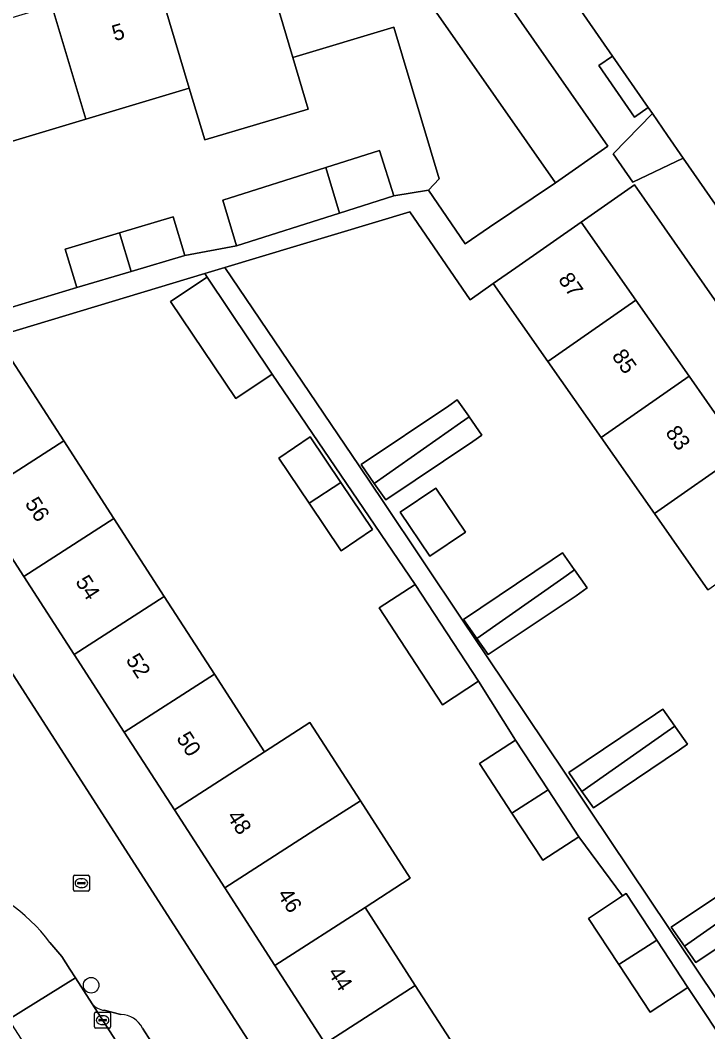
# Model space of a CAD drawing. Extents: x 159352 to 160617, y 385888 to 387323.
# Drawn here: x 159749 to 159792.3, y 386318 to 386381.5 of the extents above; entities that cross this region are included whole.
import ezdxf

# ---------------------------------------------------------------- set-up
doc = ezdxf.new("R2010")
doc.units = 0
for name, color, linetype in [('IMGEO_Boom', 7, 'Continuous'), ('IMGEO_Erf', 7, 'Continuous'), ('IMGEO_Kolk', 7, 'Continuous'), ('IMGEO_Pand', 7, 'Continuous'), ('IMGEO_Pand_nummerreeks', 7, 'Continuous'), ('IMGEO_Parkeervlak_open', 7, 'Continuous'), ('IMGEO_Rijbaan_lokaal_gesloten', 7, 'Continuous'), ('IMGEO_Rijbaan_lokaal_open', 7, 'Continuous'), ('IMGEO_Rioolput', 7, 'Continuous'), ('IMGEO_Voetpad_open', 7, 'Continuous')]:
    doc.layers.add(name, color=color, linetype=linetype)

msp = doc.modelspace()

# ---------------------------------------------------------------- linework, layer by layer
at = {"layer": 'IMGEO_Boom'}
msp.add_circle((159753.496, 386320.884), 0.489, dxfattribs=at)
at = {"layer": 'IMGEO_Erf'}
for points in [[(159764.051, 386386.334), (159770.708, 386388.324), (159771.938, 386384.207), (159773.381, 386384.639), (159782.695, 386371.311), (159785.983, 386373.605), (159773.422, 386391.613)], [(159746.351, 386362.856), (159752.592, 386364.728), (159751.872, 386367.146), (159755.287, 386368.163), (159758.658, 386369.167), (159759.378, 386366.749), (159762.637, 386367.359), (159761.779, 386370.231), (159768.247, 386372.277), (159771.626, 386373.346), (159772.53, 386370.489), (159774.705, 386370.856), (159775.37, 386371.561), (159772.522, 386381.09), (159766.182, 386379.195), (159767.151, 386375.948), (159760.638, 386374.003), (159759.669, 386377.249), (159753.156, 386375.302), (159746.642, 386373.355)], [(159815.949, 386330.644), (159787.666, 386371.193), (159784.299, 386368.844), (159787.734, 386363.946), (159791.085, 386359.167), (159794.436, 386354.389)], [(159792.268, 386345.742), (159788.917, 386350.52), (159785.566, 386355.299), (159782.215, 386360.077), (159778.781, 386364.974), (159777.332, 386363.957), (159773.534, 386369.495), (159761.909, 386365.991), (159770.355, 386353.528), (159771.86, 386351.282), (159776.851, 386343.834), (159778.356, 386341.588), (159783.346, 386334.141), (159784.851, 386331.895), (159789.842, 386324.447), (159791.347, 386322.201), (159794.738, 386317.142)], [(159793.797, 386316.542), (159791.022, 386320.752), (159788.643, 386319.195), (159786.671, 386322.188), (159784.762, 386325.083), (159786.901, 386326.492), (159784.156, 386330.214), (159781.898, 386328.735), (159779.953, 386331.706), (159777.919, 386334.812), (159780.178, 386336.291), (159777.843, 386339.993), (159775.585, 386338.514), (159771.606, 386344.591), (159773.865, 386346.07), (159764.875, 386359.296), (159762.584, 386357.757), (159758.495, 386363.843), (159760.786, 386365.382), (159760.635, 386365.607), (159738.213, 386358.849), (159740.771, 386352.514), (159758.089, 386325.63), (159772.624, 386303.066)], [(159768.209, 386317.23), (159765.052, 386322.12), (159761.895, 386327.009), (159758.737, 386331.898), (159755.58, 386336.788), (159752.423, 386341.677), (159749.266, 386346.566), (159746.109, 386351.455), (159742.87, 386356.47), (159747.075, 386359.177), (159748.538, 386360.118), (159751.777, 386355.101), (159754.933, 386350.211), (159758.089, 386345.322), (159761.245, 386340.432), (159764.402, 386335.542), (159767.253, 386337.404), (159770.438, 386332.472), (159773.562, 386327.616), (159770.715, 386325.763), (159773.871, 386320.873), (159777.027, 386315.983)], [(159796.983, 386325.978), (159791.522, 386322.318), (159790.807, 386323.338), (159789.97, 386324.533), (159795.478, 386328.224)]]:
    msp.add_lwpolyline(points, dxfattribs=at)
for points in [[(159772.019, 386351.388), (159771.295, 386352.422), (159770.466, 386353.604), (159775.992, 386357.305), (159776.517, 386357.673), (159777.238, 386356.644), (159777.264, 386356.607), (159778.068, 386355.459), (159777.497, 386355.059)], [(159769.209, 386348.188), (159767.197, 386351.181), (159765.296, 386354.01), (159767.275, 386355.34), (159769.202, 386352.471), (159771.187, 386349.517)], [(159774.782, 386347.846), (159772.931, 386350.608), (159775.177, 386352.113), (159777.027, 386349.351)], [(159782.487, 386347.611), (159783.132, 386348.063), (159783.867, 386347.014), (159783.89, 386346.982), (159784.683, 386345.85), (159783.992, 386345.365), (159778.462, 386341.659), (159777.748, 386342.677), (159776.91, 386343.872)], [(159788.982, 386337.918), (159789.444, 386338.242), (159790.202, 386337.161), (159790.235, 386337.112), (159790.995, 386336.028), (159790.487, 386335.672), (159785.072, 386332.043), (159784.357, 386333.063), (159783.521, 386334.256)]]:
    msp.add_lwpolyline(points, close=True, dxfattribs=at)
at = {"layer": 'IMGEO_Kolk'}
for p, q in [((159753.791, 386319.189), (159754.643, 386319.189)), ((159753.716, 386318.263), (159753.716, 386319.115)), ((159753.975, 386318.683), (159753.975, 386318.695)), ((159754.413, 386318.646), (159754.015, 386318.646)), ((159754.018, 386318.732), (159754.416, 386318.732)), ((159754.204, 386318.969), (159754.229, 386318.969)), ((159754.459, 386318.695), (159754.459, 386318.683)), ((159754.717, 386319.115), (159754.717, 386318.263)), ((159754.643, 386318.189), (159753.791, 386318.189)), ((159754.227, 386318.409), (159754.202, 386318.409))]:
    msp.add_line(p, q, dxfattribs=at)
for points in [[(159753.791, 386319.189), (159754.643, 386319.189)], [(159753.716, 386318.263), (159753.716, 386319.115)], [(159754.717, 386319.115), (159754.717, 386318.263)], [(159754.643, 386318.189), (159753.791, 386318.189)]]:
    msp.add_lwpolyline(points, dxfattribs=at)
for centre, radius, start, end in [((159753.793, 386319.113), 0.0765, 91.55205, 178.44795), ((159753.793, 386319.113), 0.0765, 91.55205, 178.44795), ((159754.641, 386319.113), 0.0765, 1.55205, 88.44795), ((159754.641, 386319.113), 0.0765, 1.55205, 88.44795), ((159754.015, 386318.692), 0.0403, 85.87752, 175.75265), ((159754.012, 386318.682), 0.0366, 178.93798, 274.71019), ((159754.416, 386318.689), 0.043, 264.86636, 352.45326), ((159754.42, 386318.694), 0.0386, 1.73085, 96.63898), ((159753.793, 386318.265), 0.0765, 181.55205, 268.44795), ((159753.793, 386318.265), 0.0765, 181.55205, 268.44795), ((159754.641, 386318.265), 0.0765, 271.55205, 358.44795), ((159754.641, 386318.265), 0.0765, 271.55205, 358.44795)]:
    msp.add_arc(centre, radius, start, end, dxfattribs=at)
for centre, major_axis, ratio, start_param, end_param in [((159754.203, 386318.689), (-0.387, 0.002), 0.722429, 4.712389, 7.853982), ((159754.228, 386318.689), (-0.39, 0.002), 0.717154, 1.570796, 4.712389)]:
    msp.add_ellipse(centre, major_axis=major_axis, ratio=ratio, start_param=start_param, end_param=end_param, dxfattribs=at)
at = {"layer": 'IMGEO_Pand'}
for points in [[(159766.182, 386379.195), (159772.522, 386381.09), (159775.37, 386371.561), (159774.705, 386370.856), (159777.015, 386367.477), (159778.551, 386368.514), (159782.695, 386371.311), (159773.381, 386384.639), (159771.938, 386384.207), (159770.708, 386388.324), (159764.051, 386386.334)], [(159764.051, 386386.334), (159757.538, 386384.388), (159759.669, 386377.249), (159760.638, 386374.003), (159767.151, 386375.948), (159766.182, 386379.195)], [(159757.538, 386384.388), (159751.025, 386382.441), (159753.156, 386375.302), (159759.669, 386377.249)], [(159746.642, 386373.355), (159753.156, 386375.302), (159751.025, 386382.441), (159744.511, 386380.494)], [(159772.53, 386370.489), (159771.626, 386373.346), (159768.247, 386372.277), (159769.104, 386369.405)], [(159761.779, 386370.231), (159762.637, 386367.359), (159769.104, 386369.405), (159768.247, 386372.277)], [(159759.378, 386366.749), (159758.658, 386369.167), (159755.287, 386368.163), (159756.009, 386365.746)], [(159787.734, 386363.946), (159784.299, 386368.844), (159780.206, 386365.974), (159778.781, 386364.974), (159782.215, 386360.077)], [(159751.872, 386367.146), (159752.592, 386364.728), (159756.009, 386365.746), (159755.287, 386368.163)], [(159758.495, 386363.843), (159762.584, 386357.757), (159764.875, 386359.296), (159760.786, 386365.382)], [(159791.085, 386359.167), (159787.734, 386363.946), (159782.215, 386360.077), (159785.566, 386355.299)], [(159751.777, 386355.101), (159748.538, 386360.118), (159747.075, 386359.177), (159742.87, 386356.47), (159746.109, 386351.455)], [(159785.566, 386355.299), (159788.917, 386350.52), (159794.436, 386354.389), (159791.085, 386359.167)], [(159776.717, 386356.223), (159777.264, 386356.607), (159777.238, 386356.644), (159776.517, 386357.673), (159775.992, 386357.305), (159770.466, 386353.604), (159771.295, 386352.422)], [(159777.497, 386355.059), (159778.068, 386355.459), (159777.264, 386356.607), (159776.717, 386356.223), (159771.295, 386352.422), (159772.019, 386351.388)], [(159746.109, 386351.455), (159749.266, 386346.566), (159754.933, 386350.211), (159751.777, 386355.101)], [(159767.275, 386355.34), (159765.296, 386354.01), (159767.197, 386351.181), (159769.202, 386352.471)], [(159788.917, 386350.52), (159792.268, 386345.742), (159797.786, 386349.611), (159794.436, 386354.389)], [(159769.202, 386352.471), (159767.197, 386351.181), (159769.209, 386348.188), (159771.187, 386349.517)], [(159772.931, 386350.608), (159774.782, 386347.846), (159777.027, 386349.351), (159775.177, 386352.113)], [(159758.089, 386345.322), (159754.933, 386350.211), (159749.266, 386346.566), (159752.423, 386341.677)], [(159783.222, 386346.514), (159783.89, 386346.982), (159783.867, 386347.014), (159783.132, 386348.063), (159782.487, 386347.611), (159776.91, 386343.872), (159777.748, 386342.677)], [(159783.992, 386345.365), (159784.683, 386345.85), (159783.89, 386346.982), (159783.222, 386346.514), (159777.748, 386342.677), (159778.462, 386341.659)], [(159771.606, 386344.591), (159775.585, 386338.514), (159777.843, 386339.993), (159773.865, 386346.07)], [(159761.245, 386340.432), (159758.089, 386345.322), (159752.423, 386341.677), (159755.58, 386336.788)], [(159755.58, 386336.788), (159758.737, 386331.898), (159764.402, 386335.542), (159761.245, 386340.432)], [(159789.717, 386336.821), (159790.202, 386337.161), (159789.444, 386338.242), (159788.982, 386337.918), (159783.521, 386334.256), (159784.357, 386333.063)], [(159770.438, 386332.472), (159767.253, 386337.404), (159764.402, 386335.542), (159758.737, 386331.898), (159761.895, 386327.009), (159767.558, 386330.652)], [(159790.487, 386335.672), (159790.995, 386336.028), (159790.235, 386337.112), (159790.202, 386337.161), (159789.717, 386336.821), (159784.357, 386333.063), (159785.072, 386332.043)], [(159780.178, 386336.291), (159777.919, 386334.812), (159779.953, 386331.706), (159782.224, 386333.166)], [(159781.898, 386328.735), (159784.156, 386330.214), (159782.224, 386333.166), (159779.953, 386331.706)], [(159770.438, 386332.472), (159767.558, 386330.652), (159761.895, 386327.009), (159765.052, 386322.12), (159770.715, 386325.763), (159773.562, 386327.616)], [(159796.213, 386327.127), (159796.833, 386327.562), (159796.076, 386328.643), (159795.478, 386328.224), (159789.97, 386324.533), (159790.807, 386323.338)], [(159796.983, 386325.978), (159796.213, 386327.127), (159790.807, 386323.338), (159791.522, 386322.318)], [(159786.901, 386326.492), (159784.762, 386325.083), (159786.671, 386322.188), (159789.063, 386323.725), (159787.137, 386326.648)], [(159773.871, 386320.873), (159770.715, 386325.763), (159765.052, 386322.12), (159768.209, 386317.23)], [(159789.063, 386323.725), (159786.671, 386322.188), (159788.643, 386319.195), (159791.022, 386320.752)], [(159768.209, 386317.23), (159771.366, 386312.341), (159777.027, 386315.983), (159773.871, 386320.873)]]:
    msp.add_lwpolyline(points, close=True, dxfattribs=at)
at = {"layer": 'IMGEO_Parkeervlak_open'}
for points in [[(159753.56, 386319.71), (159791.707, 386260.356)], [(159755.374, 386319.05), (159754.322, 386319.308)], [(159791.331, 386264.428), (159771.07, 386295.893), (159769.144, 386298.883), (159768.113, 386300.485), (159766.159, 386303.52), (159756.717, 386318.183)]]:
    msp.add_lwpolyline(points, dxfattribs=at)
for centre, radius, start, end in [((159754.46, 386320.492), 1.192, 221.00835, 263.36307), ((159755.329, 386317.506), 1.545, 25.99201, 88.31787)]:
    msp.add_arc(centre, radius, start, end, dxfattribs=at)
at = {"layer": 'IMGEO_Rijbaan_lokaal_gesloten'}
msp.add_lwpolyline([(159772.135, 386399.664), (159786.274, 386379.271), (159788.514, 386376.04), (159788.78, 386375.657), (159789.737, 386374.277), (159790.721, 386372.862), (159806.321, 386350.42)], dxfattribs=at)
at = {"layer": 'IMGEO_Rijbaan_lokaal_open'}
msp.add_lwpolyline([(159748.295, 386318.74), (159752.513, 386321.34), (159752.155, 386321.898), (159751.651, 386322.683), (159750.909, 386323.567)], dxfattribs=at)
msp.add_lwpolyline([(159753.56, 386319.71), (159752.513, 386321.34), (159748.295, 386318.74), (159758.148, 386303.438), (159760.892, 386299.177), (159787.704, 386257.403), (159787.911, 386257.081), (159792.063, 386259.851), (159791.888, 386260.1), (159791.707, 386260.356)], close=True, dxfattribs=at)
msp.add_arc((159741.546, 386316.454), 11.759, 37.22296, 72.80476, dxfattribs=at)
at = {"layer": 'IMGEO_Rioolput'}
for p, q in [((159752.383, 386326.873), (159752.383, 386327.725)), ((159752.458, 386327.799), (159753.31, 386327.799)), ((159752.871, 386327.579), (159752.896, 386327.579)), ((159753.384, 386327.725), (159753.384, 386326.873)), ((159752.642, 386327.293), (159752.642, 386327.305)), ((159753.08, 386327.256), (159752.682, 386327.256)), ((159752.685, 386327.342), (159753.083, 386327.342)), ((159752.894, 386327.019), (159752.869, 386327.019)), ((159753.126, 386327.305), (159753.126, 386327.293)), ((159753.31, 386326.799), (159752.458, 386326.799))]:
    msp.add_line(p, q, dxfattribs=at)
for points in [[(159752.383, 386326.873), (159752.383, 386327.725)], [(159752.458, 386327.799), (159753.31, 386327.799)], [(159753.384, 386327.725), (159753.384, 386326.873)], [(159753.31, 386326.799), (159752.458, 386326.799)]]:
    msp.add_lwpolyline(points, dxfattribs=at)
for centre, radius, start, end in [((159752.46, 386327.723), 0.0765, 91.55205, 178.44795), ((159752.46, 386327.723), 0.0765, 91.55205, 178.44795), ((159753.308, 386327.723), 0.0765, 1.55205, 88.44795), ((159753.308, 386327.723), 0.0765, 1.55205, 88.44795), ((159752.46, 386326.875), 0.0765, 181.55205, 268.44795), ((159752.46, 386326.875), 0.0765, 181.55205, 268.44795), ((159752.682, 386327.302), 0.0403, 85.87752, 175.75265), ((159752.679, 386327.292), 0.0366, 178.93798, 274.71019), ((159753.083, 386327.299), 0.043, 264.86636, 352.45326), ((159753.087, 386327.304), 0.0386, 1.73085, 96.63898), ((159753.308, 386326.875), 0.0765, 271.55205, 358.44795), ((159753.308, 386326.875), 0.0765, 271.55205, 358.44795)]:
    msp.add_arc(centre, radius, start, end, dxfattribs=at)
for centre, major_axis, ratio, start_param, end_param in [((159752.87, 386327.299), (-0.387, 0.002), 0.722429, 4.712389, 7.853982), ((159752.895, 386327.299), (-0.39, 0.002), 0.717154, 1.570796, 4.712389)]:
    msp.add_ellipse(centre, major_axis=major_axis, ratio=ratio, start_param=start_param, end_param=end_param, dxfattribs=at)
at = {"layer": 'IMGEO_Voetpad_open'}
for points in [[(159806.321, 386350.42), (159790.721, 386372.862), (159787.552, 386371.356), (159786.32, 386373.122), (159788.78, 386375.657), (159788.514, 386376.04), (159787.659, 386375.447), (159785.419, 386378.678), (159786.274, 386379.271), (159772.135, 386399.664), (159771.719, 386400.218), (159771.256, 386400.732), (159770.748, 386401.203), (159770.2, 386401.627), (159769.617, 386402), (159769.003, 386402.319), (159768.362, 386402.582), (159767.701, 386402.788), (159764.562, 386401.86), (159764.565, 386401.845)], [(159773.422, 386391.613), (159785.983, 386373.605), (159782.695, 386371.311), (159778.551, 386368.514), (159777.015, 386367.477), (159774.705, 386370.856), (159772.53, 386370.489), (159769.104, 386369.405), (159762.637, 386367.359), (159759.378, 386366.749), (159756.009, 386365.746), (159752.592, 386364.728), (159746.351, 386362.856)], [(159738.213, 386358.849), (159760.635, 386365.607), (159761.909, 386365.991), (159773.534, 386369.495), (159777.332, 386363.957), (159778.781, 386364.974), (159780.206, 386365.974), (159784.299, 386368.844), (159787.666, 386371.193)], [(159787.666, 386371.193), (159815.949, 386330.644), (159816.573, 386329.75), (159844.806, 386289.272), (159847.524, 386285.715)], [(159794.738, 386317.142), (159791.347, 386322.201), (159789.842, 386324.447), (159784.851, 386331.895), (159783.346, 386334.141), (159778.356, 386341.588), (159776.851, 386343.834), (159771.86, 386351.282), (159770.355, 386353.528), (159761.909, 386365.991), (159760.635, 386365.607), (159760.786, 386365.382), (159764.875, 386359.296), (159773.865, 386346.07), (159777.843, 386339.993), (159780.178, 386336.291), (159782.224, 386333.166), (159784.156, 386330.214), (159786.901, 386326.492), (159787.137, 386326.648), (159789.063, 386323.725), (159791.022, 386320.752), (159793.797, 386316.542)], [(159791.707, 386260.356), (159791.888, 386260.1), (159797.832, 386263.932), (159773.364, 386301.917), (159772.624, 386303.066), (159758.089, 386325.63), (159740.771, 386352.514)], [(159750.909, 386323.567), (159751.651, 386322.683), (159752.155, 386321.898), (159752.513, 386321.34), (159753.56, 386319.71)], [(159754.322, 386319.308), (159755.374, 386319.05)], [(159756.717, 386318.183), (159766.159, 386303.52), (159767.033, 386304.083), (159768.987, 386301.048), (159768.113, 386300.485), (159769.144, 386298.883), (159770.102, 386299.514), (159771.871, 386296.931), (159771.07, 386295.893), (159791.331, 386264.428)]]:
    msp.add_lwpolyline(points, dxfattribs=at)
for points in [[(159786.274, 386379.271), (159785.419, 386378.678), (159787.659, 386375.447), (159788.514, 386376.04)], [(159790.721, 386372.862), (159789.737, 386374.277), (159788.78, 386375.657), (159786.32, 386373.122), (159787.552, 386371.356)]]:
    msp.add_lwpolyline(points, close=True, dxfattribs=at)
for centre, radius, start, end in [((159741.546, 386316.454), 11.759, 37.22296, 72.80476), ((159754.46, 386320.492), 1.192, 221.00835, 263.36307), ((159755.329, 386317.506), 1.545, 25.99201, 88.31787)]:
    msp.add_arc(centre, radius, start, end, dxfattribs=at)

# ---------------------------------------------------------------- texts
at = {"layer": 'IMGEO_Pand_nummerreeks'}
for s, rotation, p in [('5', 16.63994, (159754.98, 386380.2)), ('87', 305.04007, (159782.825, 386365.233)), ('85', 305.04007, (159786.196, 386360.424)), ('83', 305.04007, (159789.568, 386355.616)), ('56', 302.85243, (159749.3, 386351.158)), ('54', 302.85243, (159752.474, 386346.243)), ('52', 302.85243, (159755.646, 386341.33)), ('50', 302.85243, (159758.823, 386336.41)), ('48', 302.85319, (159761.997, 386331.495)), ('46', 302.85319, (159765.17, 386326.582)), ('44', 302.85243, (159768.344, 386321.667))]:
    msp.add_text(s, height=1, rotation=rotation, dxfattribs=at).set_placement(p)

doc.saveas('drawing.dxf')
